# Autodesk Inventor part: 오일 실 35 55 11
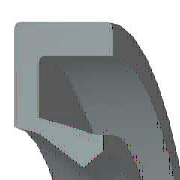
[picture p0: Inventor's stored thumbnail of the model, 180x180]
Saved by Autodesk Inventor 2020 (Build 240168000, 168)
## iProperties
Created: 2012-02
Part Number: 오일 실 35 55 11
Material: 고무
Description: 오일 실 - 비스프링, 조립 GA
Document SubType Name: Modeling
Standard: JIS B 2402
Designer: mdu-01
Standards Organization: JIS
Language: ko-KR
Size Designation: 35 55 11 A
Categories: <MemberInstance><Categories><Category DisplayName="샤프트 부품" InternalName="7f7aeb1f-a693-4053-b835-cee3144e0d98" Mnemonic="SHFT"><Category DisplayName="실링" Intern
Density: 0.93 g/cm^3
Appearance: Rubber-Black
IsCustomPart: 1
Author: mdu-01
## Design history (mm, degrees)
body "Solid1"
revolve "회전1" stored, may be unused: angle "d27" = 360 deg
fillet "모깎기1" dims "d28" = 0.55 (= 0.05 x b)
sketch "스케치2"
  geometry: L1 (20.786, -8.25)-(21.786, -11); L2 (19.452, -7.563)-(20.786, -8.25); L3 (17.5, -3.025)-(19.452, -7.563); L4 (19.038, -1.65)-(17.5, -3.025); L5 (23.5, -9.625)-(19.038, -1.65); L6 (23.5, -0.55)-(23.5, -9.625); L7 (25.5, -0.55)-(23.5, -0.55); L8 (25.5, 0)-(25.5, -0.55); L9 (27.5, 0)-(25.5, 0); L10 (27.5, -11)-(27.5, 0); L11 (21.786, -11)-(27.5, -11); L12 (0, -9.6)-(0, 1.6) reference; L13 (28, 0)-(14, 0) reference
  constraints: 22 end point, 3 horizontal, 3 vertical
  dimensions: "d2" = 11 distance of L10.start L9.start (= b); "d4" = 2 distance of L9.start L8.start (= 0.1 x dd - 0.1 x Diam); "d6" = 0.55 distance of L8.start L7.start (= 0.05 x b); "d8" = 1.53846 horizontal distance of L4.start L3.start (= 0.0769231 x dd - 0.0769231 x Diam); "d10" = 1.375 vertical distance of L5.start L10.start (= 0.125 x b); "d12" = 2 distance of L7.start L6.start (= 0.1 x dd - 0.1 x Diam); "d14" = 1.1 vertical distance of L4.start L6.start (= 0.1 x b); "d16" = 5.71429 distance of L1.end L10.start (= 0.285714 x dd - 0.285714 x Diam); "d18" = 1 horizontal distance of L1.start L1.end (= 0.05 x dd - 0.05 x Diam); "d20" = 1.375 vertical distance of L4.start L3.start (= 0.125 x b); "d22" = 2.75 vertical distance of L1.start L1.end (= 0.25 x b); "d24" = 1.33333 horizontal distance of L2.start L1.start (= 0.0666667 x dd - 0.0666667 x Diam); "d26" = 0.6875 vertical distance of L2.start L1.start (= 0.0625 x b); "d29" = 0 distance between parallel lines of L13 L9; "d30" = 17.5 distance from line of L3.start L12 (= 0.5 x Diam); "d31" = 27.5 distance between parallel lines of L12 L10 (= 0.5 x dd)
other parameters: "dd" = 55 [user parameter; used in 7 equation terms], "Diam" = 35 [user parameter; used in 7 equation terms], "b" = 11 [user parameter; used in 8 equation terms], "d1" = 8 (derived), "d3" = 2 (derived), "d5" = 0.4 (derived), "d7" = 1.53846 (derived), "d9" = 1 (derived), "d11" = 2 (derived), "d13" = 0.8 (derived), "d15" = 5.71429 (derived), "d17" = 1 (derived), "d19" = 1 (derived), "d21" = 2 (derived), "d23" = 1.33333 (derived), "d25" = 0.5 (derived), "d32" = 0
